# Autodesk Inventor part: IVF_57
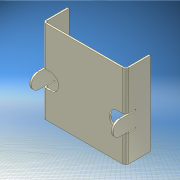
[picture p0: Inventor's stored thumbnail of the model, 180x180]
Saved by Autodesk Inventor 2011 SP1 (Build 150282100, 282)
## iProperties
Created: 2010-09
Part Number: IVF_57
Material: Standard
Document SubType Name: Blech
Designer: Gawin
Density: 1 g/cm^3
Sheet Metal Rule: Standard_mm
Flat Pattern Width: 10 cm
Flat Pattern Length: 15.3048 cm
Flat Pattern Area: 153.048 cm^2
Sheet Metal Width: 100,000 mm
Sheet Metal Length: 153,048 mm
Sheet Metal Area: 15304,779 mm^2
Author: Gawin
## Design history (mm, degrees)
node "Konturlasche1"
  sketch "Skizze1"
    geometry: L1 (0, 0)-(50, 0); L2 (50, 0)-(50, 30)
    constraints: 4 end point, 1 horizontal, 1 perpendicular
    dimensions: "d0" = 50 distance of L1.start L1.end; "d1" = 30 distance of L1.end L2.end
sketch "Skizze2"
  geometry: L1 (67.337, -17.475)-(67.337, -36.11); L2 (47.337, -17.475)-(47.337, -36.11); L3 (66.337, -17.475)-(66.337, -36.11); L4 (48.337, -36.11)-(48.337, -17.475); L5 (67.337, -17.475)-(66.337, -17.475); L6 (66.337, -17.475)-(48.337, -17.475); L7 (48.337, -17.475)-(47.337, -17.475); A1 r 10 centre (57.337, -36.11) between (47.337, -36.11) and (67.337, -36.11); A2 r 9 centre (57.337, -36.11) between (48.337, -36.11) and (66.337, -36.11); 2 further points
  constraints: 14 end point, 4 point on circle, 2 centre point, 2 collinear, 2 horizontal alignment, 2 parallel, 1 perpendicular, 1 vertical, 2 other
  dimensions: "d12" = 20 distance between parallel lines of L2 L1; "d13" = 1 distance between parallel lines of L1 L3
feature "Ausklinkung1" dims "d14" = 2 (= Stärke), "d15" = 0
node "Fläche1"
mirror "Spiegeln1"
node "Volumenkörper1"
feature "Grobblech1" dims "d2" = 2 (= BreiteBiegungsfreistellung), "d3" = 1 (= TiefeBiegungsfreistellung), "d4" = 4 (= MinimalRest), "d5" = 2 (= Biegeradius), "d6" = 100, "d7" = 2 (= Biegeradius), "d8" = 2, "d9" = 8 (= GrößeEckenfreistellung), "d10" = 2 (= Abstandsgröße), "d11" = 2 (= JacobiRadiusGröße), "Stärke" = 2 (derived), "AbstandVerbindung" = 0.01
feature "Biegung1" dims "d2" = 2 (= BreiteBiegungsfreistellung), "d3" = 1 (= TiefeBiegungsfreistellung), "d4" = 4 (= MinimalRest), "d5" = 2 (= Biegeradius), "d7" = 2 (= Biegeradius), "d8" = 2, "Stärke" = 2 (derived), "AbstandVerbindung" = 0.01
feature "Ecke1" dims "d8" = 2, "d9" = 8 (= GrößeEckenfreistellung), "d10" = 2 (= Abstandsgröße), "d11" = 2 (= JacobiRadiusGröße)
feature "Grobblech2" dims "d16" = 2 (= Biegeradius), "d17" = 2 (= BreiteBiegungsfreistellung), "d19" = 4 (= MinimalRest), "Stärke" = 2 (derived)
feature "Biegung2" dims "d16" = 2 (= Biegeradius), "d17" = 2 (= BreiteBiegungsfreistellung), "d18" = 1 (= TiefeBiegungsfreistellung), "d19" = 4 (= MinimalRest), "d20" = 2 (= Biegeradius), "Stärke" = 2 (derived), "AbstandVerbindung" = 0.01
feature "Definition1"
other parameters: "KFaktor" = 4.4, "Biegeradius" = 2 (= Stärke), "BreiteBiegungsfreistellung" = 2 (= Stärke), "TiefeBiegungsfreistellung" = 1 (= 0.5 x Stärke), "GrößeEckenfreistellung" = 8 (= 4 x Stärke), "MinimalRest" = 4 (= 2 x Stärke), "Übergangsradius" = 2 (= Biegeradius), "JacobiRadiusGröße" = 2 (= Biegeradius), "Abstandsgröße" = 2 (= Stärke), "Abstandsgröße" = 2, "Biegeradius" = 2, "BreiteBiegungsfreistellung" = 2, "GrößeEckenfreistellung" = 8, "JacobiRadiusGröße" = 2, "MinimalRest" = 4, "Stärke" = 2, "TiefeBiegungsfreistellung" = 1, "Übergangsradius" = 2
